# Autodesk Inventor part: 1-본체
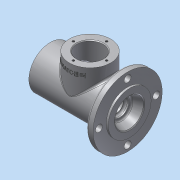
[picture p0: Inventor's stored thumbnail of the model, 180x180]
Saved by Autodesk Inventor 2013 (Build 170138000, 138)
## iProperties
Created: 2016-08
Part Number: 1-본체
Material: 알루미늄 6061
Document SubType Name: Modeling
Designer: Administrator
Density: 2.71 g/cm^3
Mass: 736.795 g
Surface Area: 619.338 cm^2
Volume: 271.88 cm^3
Author: Administrator
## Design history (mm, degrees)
sketch "스케치3"
  geometry: L1 (-57.5, 0)-(57.5, 0); L2 (-28.391, 31)-(57.5, 31); L3 (57.5, 31)-(57.5, 21); L4 (57.5, 21)-(43.5, 16); L5 (43.5, 16)-(43.5, 12.5); L6 (43.5, 12.5)-(38.5, 12.5); L7 (38.5, 12.5)-(38.5, 10); L8 (38.5, 10)-(31.2, 10); L9 (31.2, 10)-(31.2, 16.5); L10 (31.2, 16.5)-(28.5, 16.5); L11 (28.5, 16.5)-(28.5, 17.5); L12 (28.5, 17.5)-(19, 17.5); L13 (19, 17.5)-(19, 26); L14 (19, 26)-(-19, 26); L15 (-19, 26)-(-19, 17.5); L16 (-19, 17.5)-(-31.5, 17.5); L17 (-31.5, 17.5)-(-31.5, 18.5); L18 (-31.5, 18.5)-(-33.25, 18.5); L19 (-33.25, 18.5)-(-33.25, 17.5); L20 (-33.25, 17.5)-(-36.5, 17.5); L21 (-36.5, 17.5)-(-36.5, 20); L22 (-36.5, 20)-(-45.5, 20); L23 (-45.5, 20)-(-45.5, 24); L24 (-45.5, 24)-(-48.5, 24); L25 (-57.5, 12.702)-(-57.5, 31); L26 (-57.5, 31)-(-28.391, 31); L27 (-57.5, 12.702)-(-57.5, 0); L28 (-48.5, 24)-(-48.5, 0); L29 (-48.5, 0)-(-57.5, 0); 3 further points
  constraints: 58 end point, 18 parallel, 6 perpendicular, 3 vertical alignment, 2 horizontal alignment, 2 midpoint, 1 coincident, 1 collinear, 1 horizontal, 1 point on line
  dimensions: "d40" = 42 diameter of L3.end L1; "d43" = 62 diameter of L2 L1; "d44" = 32 diameter of L4.end L1; "d45" = 48 diameter of L24.end L1; "d46" = 40 diameter of L22 L1; "d47" = 35 diameter of L20 L1; "d48" = 37 diameter of L18 L1; "d49" = 25 diameter of L6.end L1; "d50" = 20 diameter of L8 L1; "d51" = 33 diameter of L10 L1; "d52" = 26 distance from line of L16.end L25; "d53" = 12 distance between parallel lines of L23 L25; "d54" = 115 distance of L1.start L1.end; "d55" = 3 distance between parallel lines of L23 L28; "d56" = 21 distance from line of L20.end L25; "d57" = 1.75 distance of L17.end L18.end; "d58" = 14 horizontal distance of L3.end L4.end; "d59" = 5 distance of L5.end L6.end; "d60" = 7.3 distance of L7.end L8.end; "d61" = 2.7 distance of L9.end L10.end; "d62" = 38 distance of L13.end L14.end; "d63" = 52 diameter of L14 L1
revolve "회전1" sketch "스케치3" stored, may be unused: angle "d64" = 90 deg
node "작업 평면1"
sketch "스케치5"
  geometry: C1 r 50 at (0, 0); C2 r 31 at (0, 0) reference; 1 further point
  constraints: 1 centre point, 1 coincident
  dimensions: "d68" = 100 diameter of C1
extrude "돌출3" join sketch "스케치5" distance "d72" = 10; taper "d73" = 0 deg
node "작업 평면2"
sketch "스케치6"
  geometry: C1 r 30 at (0, 0); 1 further point
  constraints: 1 centre point, 1 coincident
  dimensions: "d75" = 60 diameter of C1
extrude "돌출4" join sketch "스케치6" stored distance "d77" = 10; taper "d78" = 0 deg
sketch "스케치7"
  geometry: C1 r 30 at (0, 0) reference; C2 r 19 at (0, 0)
  constraints: 1 centre point, 1 coincident
  dimensions: "d79" = 38 diameter of C2
extrude "돌출5" cut sketch "스케치7" stored distance "d81" = 10; taper "d82" = 0 deg
fillet "모깎기1" dims "d90" = 3
sketch "스케치10"
  geometry: 1 further point
fillet "모깎기2" dims "d91" = 3
fillet "모깎기3" dims "d92" = 3
chamfer "모따기1" distance "d93" = 1; stored, may be unused: second distance "d94" = 2, angle "d95" = 45 deg
sketch "스케치11" dims "d96" = 83
  geometry: C1 r 31 at (0, 0) reference; C2 r 5 at (0, 41.5); 1 further point
  constraints: 2 vertical alignment, 1 centre point, 1 coincident, 2 other
  dimensions: "d98" = 10 diameter of C2
extrude "돌출6" cut sketch "스케치11" stored distance "d99" = 10; taper "d100" = 0 deg
sketch "스케치13" dims "d104" = 48
  geometry: C1 r 30 at (0, 0) reference; C2 r 20 at (0, 0) reference; 2 further points
  constraints: 2 horizontal alignment, 1 coincident, 2 other
hole "구멍2" sketch "스케치13" at (-24, 0) diameter "d106" = 3.242; stored, may be unused: countersink angle "d110" = 90 deg, drill point angle "d112" = 118 deg; dims "d107" = 8, "d108" = 4, "d109" = 2, "d111" = 10
node "작업 평면3"
sketch "스케치14"
  geometry: L1 (-30, 49)-(30, 49) reference; L2 (-57.5, -31)-(-57.5, 31) reference; 2 further points
  constraints: 1 other
  dimensions: "d117" = 10 distance from line of point (-1.5, 39) L1; "d118" = 56 distance from line of L2 point (-1.5, 39)
feature "엠보싱1" sketch "스케치14" dims "d46" = 40, "d119" = 0.5, "d120" = 0
fillet "모깎기4" dims "d121" = 3
sketch "스케치15"
  geometry: C1 r 31 at (0, 0) reference; 1 further point
  constraints: 1 coincident
hole "구멍3" sketch "스케치15" at (0, 0) diameter "d122" = 37.129; stored, may be unused: countersink angle "d126" = 90 deg, drill point angle "d128" = 118 deg; dims "d123" = 9, "d124" = 4, "d125" = 2, "d127" = 10
fillet "모깎기5" dims "d129" = 3
chamfer "모따기2" distance "d130" = 1; stored, may be unused: second distance "d131" = 2, angle "d132" = 45 deg
fillet "모깎기6" dims "d133" = 0.3
fillet "모깎기7" dims "d134" = 2
node "솔리드2"
pattern_circular "원형 패턴1" dims angle "d102" = 360 deg
pattern_circular "원형 패턴2" dims angle "d114" = 360 deg
other parameters: "d67" = -54.5, "d74" = 49
